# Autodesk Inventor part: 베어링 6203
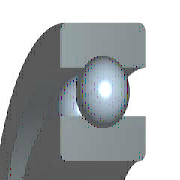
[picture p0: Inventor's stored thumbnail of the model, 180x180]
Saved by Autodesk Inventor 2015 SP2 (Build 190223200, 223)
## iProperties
IsCustomPart: 0
Created: 2009-02
Part Number: 베어링 6203
Material: 강, 연강
Description: 깊은 그루브 볼 베어링
Document SubType Name: Modeling
Standard: KS B 2023
Designer: 한국산업디자인학원 [http://gmhk.co.kr]
Standards Organization: KS
Language: ko-KR
Size Designation: 6203 - 17 x 40 x 12
Categories: <MemberInstance><Categories><Category DisplayName="샤프트 부품" InternalName="7f7aeb1f-a693-4053-b835-cee3144e0d98" Mnemonic="SHFT"><Category DisplayName="베어링" Inter
Density: 1 g/cm^3
Appearance: 크롬 - 광택
Author: pww
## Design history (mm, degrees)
sketch "스케치" dims "d0" = 5.98 (= -0.26 x WD + 0.26 x BD)
  geometry: L1 (3.01, 14.25)-(8.99, 14.25); L2 (6, 14.25)-(6, 11.26); L3 (6, 14.25)-(6, 17.24); L4 (3.778, 12.249)-(0, 12.249); L5 (0, 8.5)-(12, 8.5); L6 (3.778, 16.251)-(0, 16.251); L7 (0, 20)-(12, 20); L8 (12, 8.5)-(12, 12.249); L9 (8.222, 12.249)-(12, 12.249); L10 (8.222, 16.251)-(12, 16.251); L11 (12, 20)-(12, 16.251); L12 (-1.4, 0)-(8.4, 0) reference; L13 (0, -0.3)-(0, 5.3) reference
  constraints: 22 end point, 4 point on line, 2 collinear, 2 perpendicular, 2 symmetric about line, 1 midpoint, 1 parallel, 14 other
  dimensions: "d9" = 17 diameter of L5 L12 (= WD); "d11" = 40 diameter of L7 L12 (= BD); "d12" = 12 distance between parallel lines of L8 L13 (= KB); "d13" = 24.498 diameter of L9 L12 (= 0.326 x BD + 0.674 x WD)
revolve "본체" stored, may be unused: angle "d6" = 90 deg
revolve "볼" stored, may be unused: angle "d7" = 90 deg
pattern_circular "IDS_ARRAYBALL[SIMPL:T]" dims angle "d3" = 360 deg
sketch "스케치2"
  geometry: L1 (0, 25.741)-(24.747, 25.741); L2 (24.747, 25.741)-(24.747, -25.398); L3 (24.747, -25.398)-(0, -25.398); L4 (0, -25.398)-(0, 25.741); 1 further point
  constraints: 8 end point, 2 parallel, 1 horizontal, 1 perpendicular
extrude "돌출1" cut sketch "스케치2" distance "d25" = 123; taper "d26" = 0 deg
body "Solid1"
fillet "모깎기1" dims "d1" = 0.6 (= KRS)
other parameters: "WD" = 17 [user parameter; used in 5 equation terms], "BD" = 40 [user parameter; used in 5 equation terms], "KB" = 12 [user parameter; used in 1 equation term], "KRS" = 0.6 [user parameter; used in 1 equation term], "d4" = 0, "d5" = 0, "d8" = 0, "d14" = 0, "d15" = 0, "BBA" = 0 [user parameter], "BC0" = 4750000 [user parameter], "BC" = 9560000 [user parameter], "WR" = 8.5 (= 0.5 x WD) [user parameter]
